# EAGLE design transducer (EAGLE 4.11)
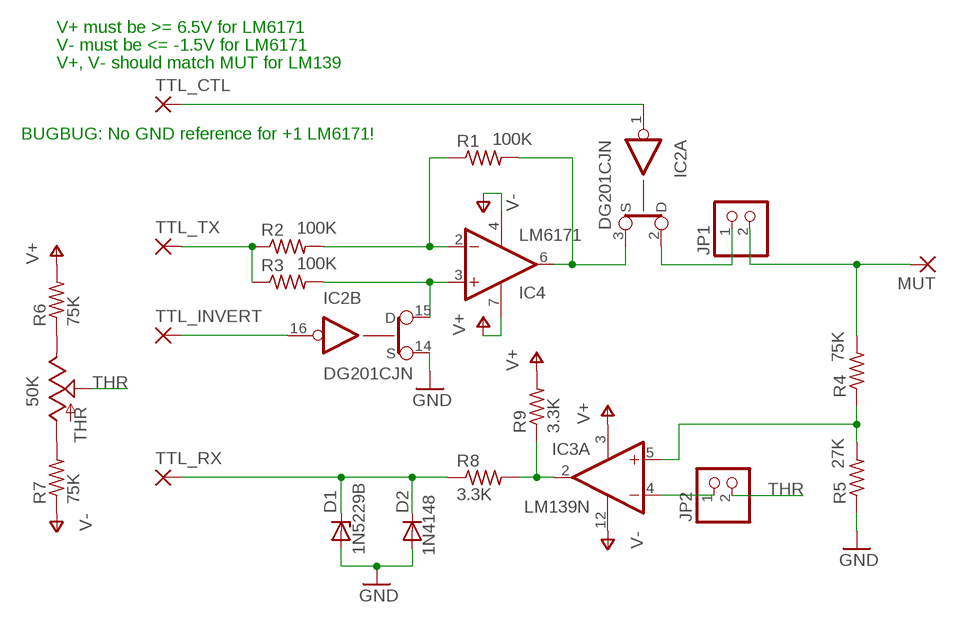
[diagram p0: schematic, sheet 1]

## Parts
D1  1N5229B  ZENER-DIODEDO35Z10  [DO35Z10]
D2  1N4148  [DO35-10]
IC2  DG201CJN  [DIL16]
IC3  LM139N  LM339N  [DIL14]
IC4  LM6171  1AMP_P7+4N  [DIL08]
JP1  PINHD-1X2  [1X02]
JP2  PINHD-1X2  [1X02]
MUT  1,6/0,9  [1,6/0,9]
R1  100K  R-US_0207/10  [0207/10]
R2  100K  R-US_0207/10  [0207/10]
R3  100K  R-US_0207/10  [0207/10]
R4  75K  R-US_0207/10  [0207/10]
R5  27K  R-US_0207/10  [0207/10]
R6  75K  R-US_0207/10  [0207/10]
R7  75K  R-US_0207/10  [0207/10]
R8  3.3K  R-US_0207/10  [0207/10]
R9  3.3K  R-US_0207/10  [0207/10]
THR  50K  TRIM_US-S43P  [SP19L]
TTL_CTL  1,6/0,9  [1,6/0,9]
TTL_INVERT  1,6/0,9  [1,6/0,9]
TTL_RX  1,6/0,9  [1,6/0,9]
TTL_TX  1,6/0,9  [1,6/0,9]

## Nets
GND: D1.A D2.A IC2.14(B:S) R5.1
N$1: R2.1 R3.1 TTL_TX.1(P)
N$2: IC2.15(B:D) IC4.3(+IN) R3.2
N$3: IC4.2(-IN) R1.1 R2.2
N$4: IC2.3(A:S) IC4.6(OUT) R1.2
N$5: IC2.2(A:D) JP1.1
N$6: JP1.2 MUT.1(P) R4.2
N$7: IC3.5(A:+IN) R4.1 R5.2
N$8: IC3.4(A:-IN) JP2.1
N$9: IC3.2(A:OUT) R8.2 R9.1
N$10: IC2.16(B:IN) TTL_INVERT.1(P)
N$11: IC2.1(A:IN) TTL_CTL.1(P)
N$12: D1.C D2.C R8.1 TTL_RX.1(P)
N$13: R6.1 THR.E
N$14: R7.2 THR.A
THR: JP2.2 THR.S
V+: IC3.3(P:V+) IC4.7(V+) R6.2 R9.2
V-: IC3.12(P:GND) IC4.4(V-) R7.1
Unconnected: IC2.6(D:S) IC2.7(D:D) IC2.8(D:IN) IC2.9(C:IN) IC2.10(C:D) IC2.11(C:S) IC3.1(B:OUT) IC3.6(B:-IN) IC3.7(B:+IN) IC3.8(C:-IN) IC3.9(C:+IN) IC3.10(D:-IN) IC3.11(D:+IN) IC3.13(D:OUT) IC3.14(C:OUT)

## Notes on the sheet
- V+ must be >= 6.5V for LM6171
- V- must be <= -1.5V for LM6171
- V+, V- should match MUT for LM139
- BUGBUG: No GND reference for +1 LM6171!

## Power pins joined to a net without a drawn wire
GND: IC2.5(P:GND)
V+: IC2.13(P:V+)
V-: IC2.4(P:V-)

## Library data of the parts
D1 = diode:ZENER-DIODE: Z-Diode
D2 = diode:1N4148: DIODE
IC2 = linear:DG201CJ: CMOS SWITCH
IC3 = linear:LM339: Low Power Low Offset Voltage Quad Comparators with open collector; LM139/LM239/LM339/LM2901/LM3302
IC4 = linear:1AMP_P7+4: OP AMP
JP1 JP2 = pinhead:PINHD-1X2: PIN HEADER
MUT TTL_CTL TTL_INVERT TTL_RX TTL_TX = wirepad:1,6/0,9: THROUGH-HOLE PAD
R1-R9 = rcl:R-US_: RESISTOR, American symbol
THR = pot:TRIM_US-: POTENTIOMETER

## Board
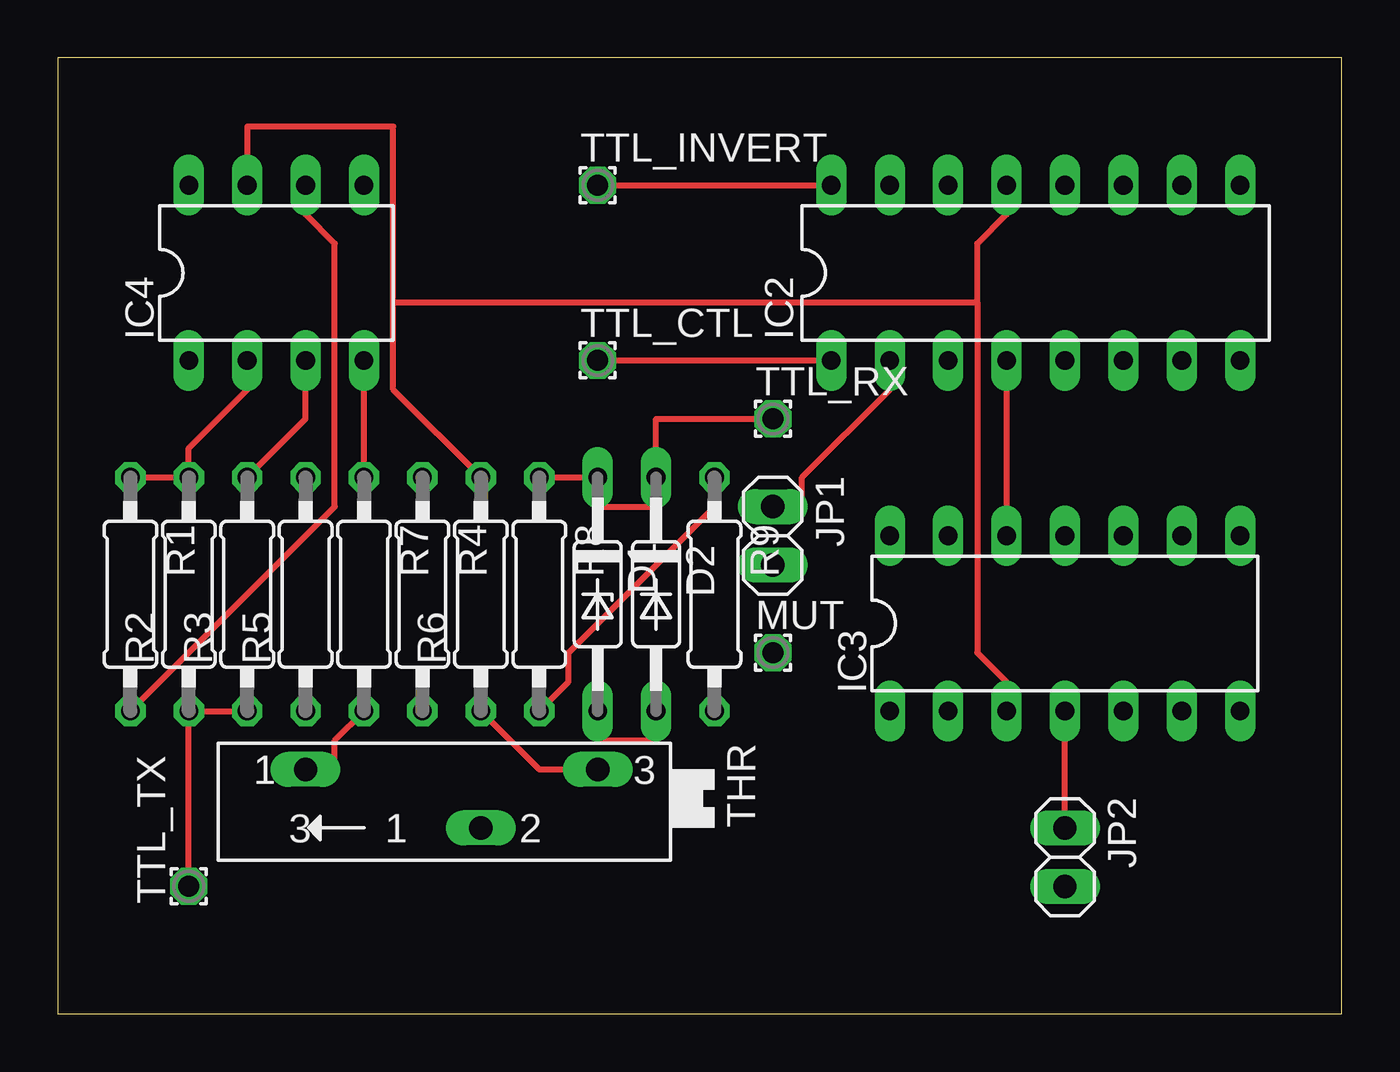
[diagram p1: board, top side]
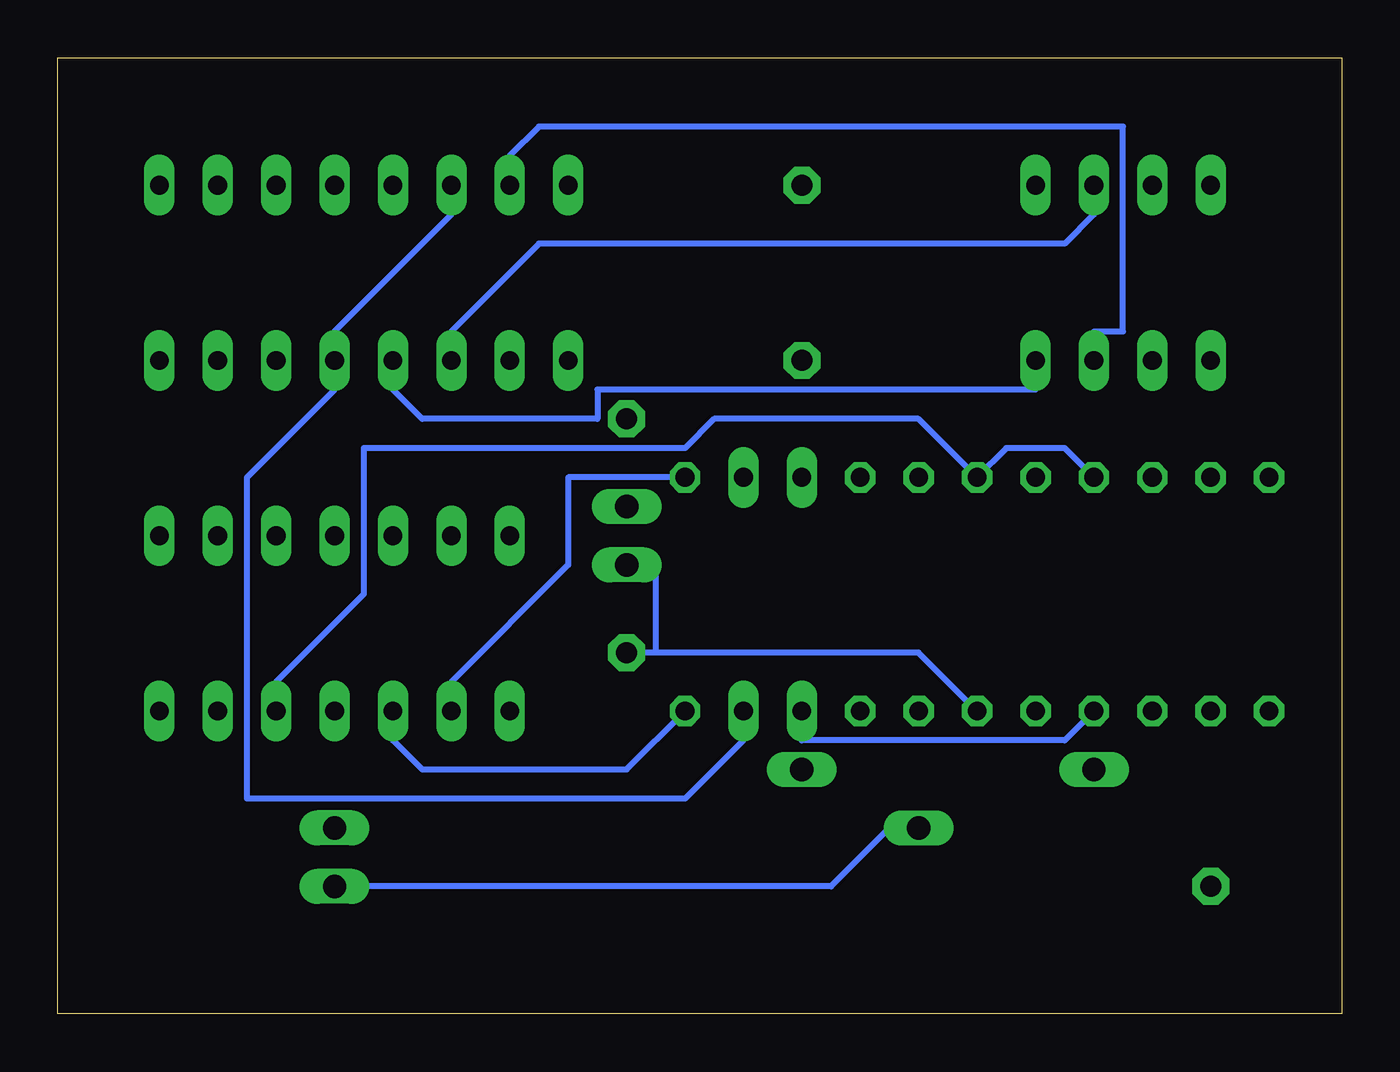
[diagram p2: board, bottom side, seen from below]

Size 55.86 x 41.58 mm. Coordinates in mm from the lower left corner, seen from the top.
Outline: 0,0 55.86,0 55.86,41.58 0,41.58 0,0
Copper layers (1*16): Top 0.035mm / dielectric 1.5mm / Bottom 0.035mm
Design rules "default": minimum track width 10mil, minimum drill 24mil, track to track 8mil, track to pad 8mil, pad to pad 8mil, via to via 8mil, smd to smd 8mil, copper to edge 40mil, drill to drill 8mil, minimum pad ring 10mil, minimum via ring 8mil, stop-mask expansion 4mil, vias tented up to drill 0mil, thermal gap 10mil

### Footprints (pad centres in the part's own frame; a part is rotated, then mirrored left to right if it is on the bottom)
DO35Z10 = drill 0.813 long: A 5.08,0; C -5.08,0
DO35-10 = drill 0.813 long: A 5.08,0; C -5.08,0
DIL16 = drill 0.813 long: 1 -8.89,-3.81; 2 -6.35,-3.81; 3 -3.81,-3.81; 4 -1.27,-3.81; 5 1.27,-3.81; 6 3.81,-3.81; 7 6.35,-3.81; 8 8.89,-3.81; 9 8.89,3.81; 10 6.35,3.81; 11 3.81,3.81; 12 1.27,3.81; 13 -1.27,3.81; 14 -3.81,3.81; 15 -6.35,3.81; 16 -8.89,3.81
DIL14 = drill 0.813 long: 1 -7.62,-3.81; 2 -5.08,-3.81; 3 -2.54,-3.81; 4 0,-3.81; 5 2.54,-3.81; 6 5.08,-3.81; 7 7.62,-3.81; 8 7.62,3.81; 9 5.08,3.81; 10 2.54,3.81; 11 0,3.81; 12 -2.54,3.81; 13 -5.08,3.81; 14 -7.62,3.81
DIL08 = drill 0.813 long: 1 -3.81,-3.81; 2 -1.27,-3.81; 3 1.27,-3.81; 4 3.81,-3.81; 5 3.81,3.81; 6 1.27,3.81; 7 -1.27,3.81; 8 -3.81,3.81
1X02 = drill 1.016 long: 1 -1.27,0; 2 1.27,0
1,6/0,9 = drill 0.914 pad 1.6 octagon: 1 0,0
0207/10 = drill 0.813 octagon: 1 -5.08,0; 2 5.08,0
SP19L = drill 1.016 long: A 5.715,-1.27; E -6.985,-1.27; S -1.905,1.27

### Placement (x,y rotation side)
D1  23.49,18.25 270 top
D2  26.03,18.25 270 top
IC2  42.54,32.22 0 top
IC3  43.81,16.98 0 top
IC4  9.52,32.22 0 top
JP1  31.11,20.79 270 top
JP2  43.81,6.82 270 top
MUT  31.11,15.71 0 top
R1  3.17,18.25 270 top
R2  5.71,18.25 90 top
R3  8.25,18.25 90 top
R4  15.87,18.25 270 top
R5  10.79,18.25 90 top
R6  18.41,18.25 90 top
R7  13.33,18.25 270 top
R8  20.95,18.25 270 top
R9  28.57,18.25 270 top
THR  16.5,9.36 180 top
TTL_CTL  23.49,28.41 0 top
TTL_INVERT  23.49,36.03 0 top
TTL_RX  31.11,25.87 0 top
TTL_TX  5.71,5.55 90 top

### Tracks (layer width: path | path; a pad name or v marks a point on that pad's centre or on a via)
GND
  Top 0.254: D2.A 26.03,11.9 23.49,11.9 D1.A
  Bottom 0.254: IC2.14 38.73,34.76 43.81,29.68 IC2.5 43.81,27.14 47.62,23.33 47.62,9.36 28.57,9.36 26.03,11.9 D2.A | R5.1 12.06,11.9 23.49,11.9 D1.A
N$1
  Top 0.254: R3.1 R2.1 TTL_TX.1
N$2
  Top 0.254: R3.2 10.79,25.87 10.79,27.14 IC4.3
  Bottom 0.254: IC2.15 36.19,37.3 34.92,38.57 9.52,38.57 9.52,29.68 10.79,29.68 IC4.3
N$3
  Top 0.254: R1.1 R2.2 5.71,24.6 8.25,27.14 IC4.2
N$4
  Top 0.254: R1.2 12.06,22.06 12.06,33.49 10.79,34.76 IC4.6
  Bottom 0.254: IC2.3 38.73,29.68 34.92,33.49 12.06,33.49 10.79,34.76 IC4.6
N$5
  Top 0.254: IC2.2 36.19,27.14 32.38,23.33 32.38,22.06 JP1.1
N$6
  Bottom 0.254: R4.2 18.41,15.71 29.84,15.71 | 29.84,15.71 MUT.1 | 29.84,15.71 29.84,19.52 JP1.2
N$7
  Bottom 0.254: R5.2 12.06,24.6 14.6,24.6 R4.1 18.41,25.87 27.3,25.87 28.57,24.6 42.54,24.6 42.54,18.25 46.35,14.44 IC3.5
N$8
  Top 0.254: JP2.1 43.81,11.9 IC3.4
N$9
  Top 0.254: R8.2 22.22,14.44 22.22,15.71 28.57,22.06 R9.1
  Bottom 0.254: R9.1 33.65,23.33 33.65,19.52 38.73,14.44 IC3.2
N$10
  Top 0.254: TTL_INVERT.1 IC2.16
N$11
  Top 0.254: TTL_CTL.1 IC2.1
N$12
  Top 0.254: R8.1 D1.C 23.49,22.06 26.03,22.06 D2.C 26.03,24.6 26.03,25.87 TTL_RX.1
N$13
  Top 0.254: R6.1 20.95,10.63 22.22,10.63 THR.E
N$14
  Top 0.254: R7.2 12.06,11.9 12.06,10.63 THR.A
THR
  Bottom 0.254: THR.S 19.68,8.09 22.22,5.55 42.54,5.55 JP2.2
V+
  Top 0.254: R6.2 14.6,27.14 14.6,30.95 | 14.6,30.95 14.6,38.57 8.25,38.57 8.25,37.3 IC4.7 | 40,30.95 40,15.71 41.27,14.44 IC3.3 | 40,30.95 40,33.49 41.27,34.76 IC2.13 | 14.6,30.95 40,30.95
  Bottom 0.254: R9.2 31.11,10.63 40,10.63 41.27,11.9 IC3.3
V-
  Top 0.254: R7.1 13.33,27.14 IC4.4 | IC3.12 41.27,22.06 41.27,27.14 IC2.4
  Bottom 0.254: IC4.4 13.33,27.14 32.38,27.14 32.38,25.87 40,25.87 41.27,27.14 IC2.4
